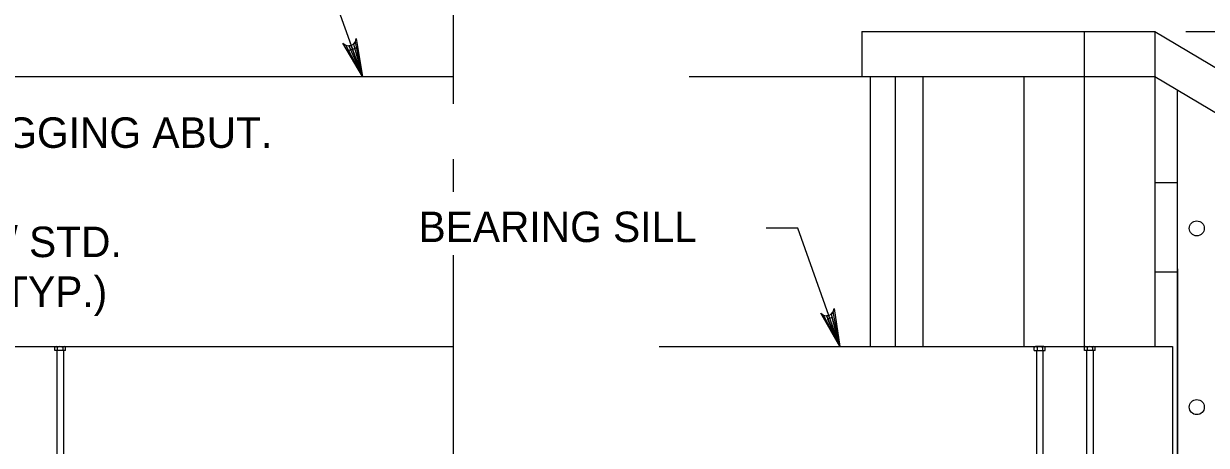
# Model space of a CAD drawing. Extents: x 635440 to 640306, y 296653 to 298484.
# Drawn here: x 639576.7 to 639693.2, y 296832.1 to 296873.6 of the extents above; entities that cross this region are included whole.
import ezdxf

# ---------------------------------------------------------------- set-up
doc = ezdxf.new("R2010")
doc.units = 0
for name, color, linetype in [('3', 7, 'Continuous'), ('4', 7, 'Continuous'), ('5', 7, 'Continuous')]:
    doc.layers.add(name, color=color, linetype=linetype)

msp = doc.modelspace()

# ---------------------------------------------------------------- linework, layer by layer
at = {"layer": '3'}
for p, q in [((639659.26, 296872.79), (639688.15, 296872.79)), ((639659.26, 296872.79), (639659.26, 296868.36)), ((639681.17, 296872.79), (639681.17, 296868.36)), ((639688.15, 296872.79), (639776.08, 296820.36)), ((639688.15, 296872.79), (639688.15, 296868.36)), ((639483.38, 296868.36), (639618.98, 296868.36)), ((639642.25, 296868.36), (639688.15, 296868.36)), ((639660.08, 296868.36), (639660.08, 296841.79)), ((639662.54, 296868.36), (639662.54, 296841.79)), ((639665.29, 296868.36), (639665.29, 296841.79)), ((639675.24, 296868.36), (639675.24, 296841.79)), ((639681.17, 296868.36), (639681.17, 296841.79)), ((639688.15, 296868.36), (639776.08, 296815.93)), ((639688.15, 296868.36), (639688.15, 296841.79)), ((639690.39, 296787.53), (639690.39, 296867.02)), ((639690.39, 296857.89), (639688.15, 296857.89)), ((639690.39, 296849.1), (639688.15, 296849.1)), ((639462.25, 296841.79), (639618.98, 296841.79)), ((639579.72, 296841.39), (639579.72, 296841.69)), ((639580.78, 296841.39), (639579.72, 296841.39)), ((639579.84, 296841.79), (639580.65, 296841.79)), ((639579.88, 296841.78), (639579.88, 296841.78)), ((639579.89, 296841.78), (639579.89, 296841.78)), ((639579.91, 296841.78), (639579.91, 296841.78)), ((639579.91, 296841.77), (639579.91, 296841.77)), ((639579.92, 296841.78), (639579.92, 296841.78)), ((639579.92, 296841.39), (639579.92, 296830.89)), ((639579.93, 296841.77), (639579.93, 296841.77)), ((639579.94, 296841.78), (639579.94, 296841.78)), ((639579.94, 296841.75), (639579.94, 296841.75)), ((639579.95, 296841.78), (639579.95, 296841.78)), ((639579.95, 296841.77), (639579.95, 296841.77)), ((639579.95, 296841.75), (639579.95, 296841.75)), ((639579.96, 296841.77), (639579.96, 296841.77)), ((639579.96, 296841.74), (639579.96, 296841.74)), ((639579.97, 296841.78), (639579.97, 296841.78)), ((639579.97, 296841.77), (639579.97, 296841.77)), ((639579.97, 296841.75), (639579.97, 296841.75)), ((639579.97, 296841.74), (639579.97, 296841.74)), ((639579.97, 296841.72), (639579.97, 296841.72)), ((639579.97, 296841.71), (639579.97, 296841.71)), ((639579.97, 296841.69), (639579.97, 296841.39)), ((639579.98, 296841.78), (639579.98, 296841.78)), ((639579.98, 296841.77), (639579.98, 296841.77)), ((639579.98, 296841.75), (639579.98, 296841.75)), ((639579.98, 296841.74), (639579.98, 296841.74)), ((639579.98, 296841.72), (639579.98, 296841.72)), ((639579.98, 296841.71), (639579.98, 296841.71)), ((639579.99, 296841.77), (639579.99, 296841.77)), ((639579.99, 296841.74), (639579.99, 296841.74)), ((639579.99, 296841.71), (639579.99, 296841.71)), ((639580, 296841.78), (639580, 296841.78)), ((639580, 296841.75), (639580, 296841.75)), ((639580, 296841.72), (639580, 296841.72)), ((639580.01, 296841.78), (639580.01, 296841.78)), ((639580.01, 296841.77), (639580.01, 296841.77)), ((639580.01, 296841.75), (639580.01, 296841.75)), ((639580.01, 296841.74), (639580.01, 296841.74)), ((639580.01, 296841.72), (639580.01, 296841.72)), ((639580.02, 296841.77), (639580.02, 296841.77)), ((639580.02, 296841.74), (639580.02, 296841.74)), ((639580.03, 296841.78), (639580.03, 296841.78)), ((639580.03, 296841.77), (639580.03, 296841.77)), ((639580.03, 296841.75), (639580.03, 296841.75)), ((639580.03, 296841.74), (639580.03, 296841.74)), ((639580.04, 296841.78), (639580.04, 296841.78)), ((639580.04, 296841.75), (639580.04, 296841.75)), ((639580.05, 296841.77), (639580.05, 296841.77)), ((639580.06, 296841.78), (639580.06, 296841.78)), ((639580.06, 296841.77), (639580.06, 296841.77)), ((639580.06, 296841.75), (639580.06, 296841.75)), ((639580.07, 296841.78), (639580.07, 296841.78)), ((639580.07, 296841.75), (639580.07, 296841.75)), ((639580.08, 296841.77), (639580.08, 296841.77)), ((639580.09, 296841.78), (639580.09, 296841.78)), ((639580.1, 296841.78), (639580.1, 296841.78)), ((639580.1, 296841.77), (639580.1, 296841.77)), ((639580.11, 296841.77), (639580.11, 296841.77)), ((639580.12, 296841.78), (639580.12, 296841.78)), ((639580.13, 296841.78), (639580.13, 296841.78)), ((639580.15, 296841.78), (639580.15, 296841.78)), ((639580.16, 296841.78), (639580.16, 296841.78)), ((639580.18, 296841.78), (639580.18, 296841.78)), ((639580.31, 296841.78), (639580.31, 296841.78)), ((639580.32, 296841.78), (639580.32, 296841.78)), ((639580.34, 296841.78), (639580.34, 296841.78)), ((639580.35, 296841.78), (639580.35, 296841.78)), ((639580.37, 296841.78), (639580.37, 296841.78)), ((639580.37, 296841.77), (639580.37, 296841.77)), ((639580.38, 296841.78), (639580.38, 296841.78)), ((639580.39, 296841.77), (639580.39, 296841.77)), ((639580.4, 296841.78), (639580.4, 296841.78)), ((639580.41, 296841.78), (639580.41, 296841.78)), ((639580.41, 296841.77), (639580.41, 296841.77)), ((639580.41, 296841.75), (639580.41, 296841.75)), ((639580.42, 296841.77), (639580.42, 296841.77)), ((639580.43, 296841.78), (639580.43, 296841.78)), ((639580.43, 296841.77), (639580.43, 296841.77)), ((639580.43, 296841.75), (639580.43, 296841.75)), ((639580.44, 296841.78), (639580.44, 296841.78)), ((639580.44, 296841.75), (639580.44, 296841.75)), ((639580.45, 296841.77), (639580.45, 296841.77)), ((639580.45, 296841.74), (639580.45, 296841.74)), ((639580.46, 296841.78), (639580.46, 296841.78)), ((639580.46, 296841.77), (639580.46, 296841.77)), ((639580.46, 296841.75), (639580.46, 296841.75)), ((639580.46, 296841.74), (639580.46, 296841.74)), ((639580.47, 296841.78), (639580.47, 296841.78)), ((639580.47, 296841.75), (639580.47, 296841.75)), ((639580.47, 296841.72), (639580.47, 296841.72)), ((639580.48, 296841.77), (639580.48, 296841.77)), ((639580.48, 296841.74), (639580.48, 296841.74)), ((639580.49, 296841.78), (639580.49, 296841.78)), ((639580.49, 296841.77), (639580.49, 296841.77)), ((639580.49, 296841.75), (639580.49, 296841.75)), ((639580.49, 296841.74), (639580.49, 296841.74)), ((639580.49, 296841.72), (639580.49, 296841.72)), ((639580.49, 296841.71), (639580.49, 296841.71)), ((639580.5, 296841.78), (639580.5, 296841.78)), ((639580.5, 296841.75), (639580.5, 296841.75)), ((639580.5, 296841.72), (639580.5, 296841.72)), ((639580.51, 296841.77), (639580.51, 296841.77)), ((639580.51, 296841.74), (639580.51, 296841.74)), ((639580.51, 296841.71), (639580.51, 296841.71)), ((639580.51, 296841.69), (639580.51, 296841.39)), ((639580.52, 296841.78), (639580.52, 296841.78)), ((639580.52, 296841.77), (639580.52, 296841.77)), ((639580.52, 296841.75), (639580.52, 296841.75)), ((639580.52, 296841.74), (639580.52, 296841.74)), ((639580.52, 296841.72), (639580.52, 296841.72)), ((639580.53, 296841.78), (639580.53, 296841.78)), ((639580.53, 296841.75), (639580.53, 296841.75)), ((639580.54, 296841.77), (639580.54, 296841.77)), ((639580.55, 296841.78), (639580.55, 296841.78)), ((639580.55, 296841.77), (639580.55, 296841.77)), ((639580.55, 296841.75), (639580.55, 296841.75)), ((639580.56, 296841.78), (639580.56, 296841.78)), ((639580.57, 296841.78), (639580.57, 296841.78)), ((639580.57, 296841.77), (639580.57, 296841.77)), ((639580.58, 296841.39), (639580.58, 296830.89)), ((639580.59, 296841.78), (639580.59, 296841.78)), ((639580.6, 296841.78), (639580.6, 296841.78)), ((639580.78, 296841.39), (639580.78, 296841.69)), ((639639.28, 296841.79), (639689.87, 296841.79)), ((639676.26, 296841.39), (639676.26, 296841.69)), ((639676.26, 296841.39), (639677.33, 296841.39)), ((639677.2, 296841.79), (639676.39, 296841.79)), ((639676.44, 296841.78), (639676.44, 296841.78)), ((639676.45, 296841.78), (639676.45, 296841.78)), ((639676.47, 296841.78), (639676.47, 296841.78)), ((639676.47, 296841.39), (639676.47, 296830.89)), ((639676.48, 296841.77), (639676.48, 296841.77)), ((639676.49, 296841.78), (639676.49, 296841.78)), ((639676.49, 296841.77), (639676.49, 296841.77)), ((639676.5, 296841.78), (639676.5, 296841.78)), ((639676.5, 296841.75), (639676.5, 296841.75)), ((639676.51, 296841.78), (639676.51, 296841.78)), ((639676.51, 296841.77), (639676.51, 296841.77)), ((639676.51, 296841.75), (639676.51, 296841.75)), ((639676.52, 296841.77), (639676.52, 296841.77)), ((639676.52, 296841.74), (639676.52, 296841.74)), ((639676.53, 296841.78), (639676.53, 296841.78)), ((639676.53, 296841.75), (639676.53, 296841.75)), ((639676.53, 296841.72), (639676.53, 296841.72)), ((639676.54, 296841.78), (639676.54, 296841.78)), ((639676.54, 296841.77), (639676.54, 296841.77)), ((639676.54, 296841.75), (639676.54, 296841.75)), ((639676.54, 296841.74), (639676.54, 296841.74)), ((639676.54, 296841.72), (639676.54, 296841.72)), ((639676.54, 296841.71), (639676.54, 296841.71)), ((639676.54, 296841.69), (639676.54, 296841.39)), ((639676.55, 296841.77), (639676.55, 296841.77)), ((639676.55, 296841.74), (639676.55, 296841.74)), ((639676.55, 296841.71), (639676.55, 296841.71)), ((639676.56, 296841.78), (639676.56, 296841.78)), ((639676.56, 296841.75), (639676.56, 296841.75)), ((639676.56, 296841.72), (639676.56, 296841.72)), ((639676.57, 296841.78), (639676.57, 296841.78)), ((639676.57, 296841.77), (639676.57, 296841.77)), ((639676.57, 296841.75), (639676.57, 296841.75)), ((639676.57, 296841.74), (639676.57, 296841.74)), ((639676.57, 296841.72), (639676.57, 296841.72)), ((639676.58, 296841.77), (639676.58, 296841.77)), ((639676.58, 296841.74), (639676.58, 296841.74)), ((639676.59, 296841.78), (639676.59, 296841.78)), ((639676.59, 296841.75), (639676.59, 296841.75)), ((639676.6, 296841.78), (639676.6, 296841.78)), ((639676.6, 296841.77), (639676.6, 296841.77)), ((639676.6, 296841.75), (639676.6, 296841.75)), ((639676.6, 296841.74), (639676.6, 296841.74)), ((639676.61, 296841.77), (639676.61, 296841.77)), ((639676.62, 296841.78), (639676.62, 296841.78)), ((639676.62, 296841.77), (639676.62, 296841.77)), ((639676.62, 296841.75), (639676.62, 296841.75)), ((639676.63, 296841.78), (639676.63, 296841.78)), ((639676.63, 296841.75), (639676.63, 296841.75)), ((639676.64, 296841.77), (639676.64, 296841.77)), ((639676.65, 296841.78), (639676.65, 296841.78)), ((639676.65, 296841.77), (639676.65, 296841.77)), ((639676.66, 296841.78), (639676.66, 296841.78)), ((639676.67, 296841.77), (639676.67, 296841.77)), ((639676.68, 296841.78), (639676.68, 296841.78)), ((639676.69, 296841.78), (639676.69, 296841.78)), ((639676.71, 296841.78), (639676.71, 296841.78)), ((639676.72, 296841.78), (639676.72, 296841.78)), ((639676.74, 296841.78), (639676.74, 296841.78)), ((639676.87, 296841.78), (639676.87, 296841.78)), ((639676.88, 296841.78), (639676.88, 296841.78)), ((639676.9, 296841.78), (639676.9, 296841.78)), ((639676.91, 296841.78), (639676.91, 296841.78)), ((639676.93, 296841.78), (639676.93, 296841.78)), ((639676.94, 296841.78), (639676.94, 296841.78)), ((639676.94, 296841.77), (639676.94, 296841.77)), ((639676.95, 296841.77), (639676.95, 296841.77)), ((639676.96, 296841.78), (639676.96, 296841.78)), ((639676.96, 296841.77), (639676.96, 296841.77)), ((639676.97, 296841.78), (639676.97, 296841.78)), ((639676.97, 296841.75), (639676.97, 296841.75)), ((639676.98, 296841.77), (639676.98, 296841.77)), ((639676.99, 296841.78), (639676.99, 296841.78)), ((639676.99, 296841.77), (639676.99, 296841.77)), ((639676.99, 296841.75), (639676.99, 296841.75)), ((639677, 296841.78), (639677, 296841.78)), ((639677, 296841.75), (639677, 296841.75)), ((639677.01, 296841.77), (639677.01, 296841.77)), ((639677.01, 296841.74), (639677.01, 296841.74)), ((639677.02, 296841.78), (639677.02, 296841.78)), ((639677.02, 296841.77), (639677.02, 296841.77)), ((639677.02, 296841.75), (639677.02, 296841.75)), ((639677.02, 296841.74), (639677.02, 296841.74)), ((639677.03, 296841.78), (639677.03, 296841.78)), ((639677.03, 296841.75), (639677.03, 296841.75)), ((639677.03, 296841.72), (639677.03, 296841.72)), ((639677.04, 296841.77), (639677.04, 296841.77)), ((639677.04, 296841.74), (639677.04, 296841.74)), ((639677.05, 296841.78), (639677.05, 296841.78)), ((639677.05, 296841.77), (639677.05, 296841.77)), ((639677.05, 296841.75), (639677.05, 296841.75)), ((639677.05, 296841.74), (639677.05, 296841.74)), ((639677.05, 296841.72), (639677.05, 296841.72)), ((639677.05, 296841.71), (639677.05, 296841.71)), ((639677.06, 296841.78), (639677.06, 296841.78)), ((639677.06, 296841.75), (639677.06, 296841.75)), ((639677.06, 296841.72), (639677.06, 296841.72)), ((639677.07, 296841.77), (639677.07, 296841.77)), ((639677.07, 296841.77), (639677.07, 296841.77)), ((639677.07, 296841.74), (639677.07, 296841.74)), ((639677.07, 296841.74), (639677.07, 296841.74)), ((639677.07, 296841.71), (639677.07, 296841.71)), ((639677.07, 296841.71), (639677.07, 296841.71)), ((639677.07, 296841.69), (639677.07, 296841.39)), ((639677.08, 296841.78), (639677.08, 296841.78)), ((639677.08, 296841.75), (639677.08, 296841.75)), ((639677.08, 296841.72), (639677.08, 296841.72)), ((639677.09, 296841.78), (639677.09, 296841.78)), ((639677.09, 296841.77), (639677.09, 296841.77)), ((639677.09, 296841.75), (639677.09, 296841.75)), ((639677.09, 296841.74), (639677.09, 296841.74)), ((639677.1, 296841.77), (639677.1, 296841.77)), ((639677.11, 296841.78), (639677.11, 296841.78)), ((639677.11, 296841.77), (639677.11, 296841.77)), ((639677.11, 296841.75), (639677.11, 296841.75)), ((639677.12, 296841.78), (639677.12, 296841.78)), ((639677.12, 296841.39), (639677.12, 296830.89)), ((639677.13, 296841.77), (639677.13, 296841.77)), ((639677.14, 296841.78), (639677.14, 296841.78)), ((639677.15, 296841.78), (639677.15, 296841.78)), ((639677.17, 296841.78), (639677.17, 296841.78)), ((639677.33, 296841.39), (639677.33, 296841.69)), ((639681.21, 296841.39), (639681.21, 296841.69)), ((639682.27, 296841.39), (639681.21, 296841.39)), ((639681.33, 296841.79), (639682.14, 296841.79)), ((639681.37, 296841.78), (639681.37, 296841.78)), ((639681.38, 296841.78), (639681.38, 296841.78)), ((639681.4, 296841.78), (639681.4, 296841.78)), ((639681.4, 296841.77), (639681.4, 296841.77)), ((639681.41, 296841.78), (639681.41, 296841.78)), ((639681.41, 296841.39), (639681.41, 296830.89)), ((639681.42, 296841.77), (639681.42, 296841.77)), ((639681.43, 296841.78), (639681.43, 296841.78)), ((639681.43, 296841.77), (639681.43, 296841.77)), ((639681.43, 296841.75), (639681.43, 296841.75)), ((639681.44, 296841.78), (639681.44, 296841.78)), ((639681.44, 296841.75), (639681.44, 296841.75)), ((639681.45, 296841.77), (639681.45, 296841.77)), ((639681.45, 296841.74), (639681.45, 296841.74)), ((639681.46, 296841.78), (639681.46, 296841.78)), ((639681.46, 296841.77), (639681.46, 296841.77)), ((639681.46, 296841.75), (639681.46, 296841.75)), ((639681.46, 296841.74), (639681.46, 296841.74)), ((639681.46, 296841.72), (639681.46, 296841.72)), ((639681.46, 296841.71), (639681.46, 296841.71)), ((639681.46, 296841.69), (639681.46, 296841.39)), ((639681.47, 296841.78), (639681.47, 296841.78)), ((639681.47, 296841.77), (639681.47, 296841.77)), ((639681.47, 296841.75), (639681.47, 296841.75)), ((639681.47, 296841.74), (639681.47, 296841.74)), ((639681.47, 296841.72), (639681.47, 296841.72)), ((639681.47, 296841.71), (639681.47, 296841.71)), ((639681.48, 296841.77), (639681.48, 296841.77)), ((639681.48, 296841.74), (639681.48, 296841.74)), ((639681.48, 296841.71), (639681.48, 296841.71)), ((639681.49, 296841.78), (639681.49, 296841.78)), ((639681.49, 296841.75), (639681.49, 296841.75)), ((639681.49, 296841.72), (639681.49, 296841.72)), ((639681.5, 296841.78), (639681.5, 296841.78)), ((639681.5, 296841.77), (639681.5, 296841.77)), ((639681.5, 296841.75), (639681.5, 296841.75)), ((639681.5, 296841.74), (639681.5, 296841.74)), ((639681.5, 296841.72), (639681.5, 296841.72)), ((639681.51, 296841.77), (639681.51, 296841.77)), ((639681.51, 296841.74), (639681.51, 296841.74)), ((639681.52, 296841.78), (639681.52, 296841.78)), ((639681.52, 296841.77), (639681.52, 296841.77)), ((639681.52, 296841.75), (639681.52, 296841.75)), ((639681.52, 296841.74), (639681.52, 296841.74)), ((639681.53, 296841.78), (639681.53, 296841.78)), ((639681.53, 296841.75), (639681.53, 296841.75)), ((639681.54, 296841.77), (639681.54, 296841.77)), ((639681.55, 296841.78), (639681.55, 296841.78)), ((639681.55, 296841.77), (639681.55, 296841.77)), ((639681.55, 296841.75), (639681.55, 296841.75)), ((639681.56, 296841.78), (639681.56, 296841.78)), ((639681.56, 296841.75), (639681.56, 296841.75)), ((639681.57, 296841.77), (639681.57, 296841.77)), ((639681.58, 296841.78), (639681.58, 296841.78)), ((639681.58, 296841.77), (639681.58, 296841.77)), ((639681.59, 296841.78), (639681.59, 296841.78)), ((639681.6, 296841.77), (639681.6, 296841.77)), ((639681.61, 296841.78), (639681.61, 296841.78)), ((639681.62, 296841.78), (639681.62, 296841.78)), ((639681.64, 296841.78), (639681.64, 296841.78)), ((639681.65, 296841.78), (639681.65, 296841.78)), ((639681.66, 296841.78), (639681.66, 296841.78)), ((639681.8, 296841.78), (639681.8, 296841.78)), ((639681.81, 296841.78), (639681.81, 296841.78)), ((639681.83, 296841.78), (639681.83, 296841.78)), ((639681.84, 296841.78), (639681.84, 296841.78)), ((639681.86, 296841.78), (639681.86, 296841.78)), ((639681.86, 296841.77), (639681.86, 296841.77)), ((639681.87, 296841.78), (639681.87, 296841.78)), ((639681.88, 296841.77), (639681.88, 296841.77)), ((639681.89, 296841.78), (639681.89, 296841.78)), ((639681.89, 296841.77), (639681.89, 296841.77)), ((639681.9, 296841.78), (639681.9, 296841.78)), ((639681.9, 296841.75), (639681.9, 296841.75)), ((639681.91, 296841.77), (639681.91, 296841.77)), ((639681.92, 296841.78), (639681.92, 296841.78)), ((639681.92, 296841.77), (639681.92, 296841.77)), ((639681.92, 296841.75), (639681.92, 296841.75)), ((639681.93, 296841.78), (639681.93, 296841.78)), ((639681.93, 296841.75), (639681.93, 296841.75)), ((639681.94, 296841.77), (639681.94, 296841.77)), ((639681.94, 296841.74), (639681.94, 296841.74)), ((639681.95, 296841.78), (639681.95, 296841.78)), ((639681.95, 296841.77), (639681.95, 296841.77)), ((639681.95, 296841.75), (639681.95, 296841.75)), ((639681.95, 296841.74), (639681.95, 296841.74)), ((639681.96, 296841.78), (639681.96, 296841.78)), ((639681.96, 296841.75), (639681.96, 296841.75)), ((639681.96, 296841.72), (639681.96, 296841.72)), ((639681.97, 296841.78), (639681.97, 296841.78)), ((639681.97, 296841.77), (639681.97, 296841.77)), ((639681.97, 296841.75), (639681.97, 296841.75)), ((639681.97, 296841.74), (639681.97, 296841.74)), ((639681.97, 296841.72), (639681.97, 296841.72)), ((639681.98, 296841.77), (639681.98, 296841.77)), ((639681.98, 296841.74), (639681.98, 296841.74)), ((639681.98, 296841.71), (639681.98, 296841.71)), ((639681.99, 296841.78), (639681.99, 296841.78)), ((639681.99, 296841.75), (639681.99, 296841.75)), ((639681.99, 296841.72), (639681.99, 296841.72)), ((639682, 296841.78), (639682, 296841.78)), ((639682, 296841.77), (639682, 296841.77)), ((639682, 296841.75), (639682, 296841.75)), ((639682, 296841.74), (639682, 296841.74)), ((639682, 296841.72), (639682, 296841.72)), ((639682, 296841.71), (639682, 296841.71)), ((639682, 296841.69), (639682, 296841.39)), ((639682.01, 296841.77), (639682.01, 296841.77)), ((639682.01, 296841.74), (639682.01, 296841.74)), ((639682.02, 296841.78), (639682.02, 296841.78)), ((639682.02, 296841.75), (639682.02, 296841.75)), ((639682.03, 296841.77), (639682.03, 296841.77)), ((639682.04, 296841.78), (639682.04, 296841.78)), ((639682.04, 296841.77), (639682.04, 296841.77)), ((639682.04, 296841.75), (639682.04, 296841.75)), ((639682.05, 296841.78), (639682.05, 296841.78)), ((639682.06, 296841.78), (639682.06, 296841.78)), ((639682.06, 296841.77), (639682.06, 296841.77)), ((639682.07, 296841.39), (639682.07, 296830.89)), ((639682.08, 296841.78), (639682.08, 296841.78)), ((639682.09, 296841.78), (639682.09, 296841.78)), ((639682.27, 296841.39), (639682.27, 296841.69)), ((639689.87, 296841.79), (639689.87, 296822.59))]:
    msp.add_line(p, q, dxfattribs=at)
for centre in [(639692.28, 296853.42), (639692.28, 296835.83)]:
    msp.add_circle(centre, 0.738, dxfattribs=at)
for centre, radius, start, end in [((639579.85, 296841.65), 0.135, 17.4518, 162.5482), ((639580.24, 296841.36), 0.424, 51.05, 128.95), ((639580.65, 296841.64), 0.148, 91.8271, 158.7131), ((639580.65, 296841.64), 0.148, 21.2869, 91.8271), ((639676.4, 296841.64), 0.148, 88.1729, 158.7131), ((639676.4, 296841.64), 0.148, 21.2869, 88.1729), ((639676.8, 296841.36), 0.424, 51.05, 128.95), ((639677.2, 296841.65), 0.135, 17.4518, 162.5482), ((639681.34, 296841.65), 0.135, 17.4518, 162.5482), ((639681.73, 296841.36), 0.424, 51.05, 128.95), ((639682.13, 296841.64), 0.148, 91.8271, 158.7131), ((639682.13, 296841.64), 0.148, 21.2869, 91.8271)]:
    msp.add_arc(centre, radius, start, end, dxfattribs=at)
at = {"layer": '4'}
for p, q in [((639610.04, 296868.36), (639600.85, 296894.02)), ((639618.98, 296890.38), (639618.98, 296865.67)), ((639691.19, 296872.79), (639697.19, 296872.79)), ((639618.98, 296860.22), (639618.98, 296857.02)), ((639618.98, 296850.77), (639618.98, 296749.87)), ((639690.39, 296849.43), (639690.39, 296802.35))]:
    msp.add_line(p, q, dxfattribs=at)
for points in [[(639610.04, 296868.36), (639608.13, 296871.63), (639608.41, 296871.43), (639608.7, 296871.37), (639608.95, 296871.42), (639609.17, 296871.54), (639609.35, 296871.77), (639609.44, 296872.11), (639610.04, 296868.36), (639609.35, 296871.77), (639609.17, 296871.54), (639610.04, 296868.36), (639608.95, 296871.42), (639608.7, 296871.37), (639610.04, 296868.36), (639608.41, 296871.43)], [(639657.09, 296841.79), (639652.97, 296853.44), (639649.85, 296853.44)], [(639657.09, 296841.79), (639655.21, 296845.08), (639655.49, 296844.87), (639655.77, 296844.81), (639656.02, 296844.86), (639656.25, 296844.98), (639656.43, 296845.2), (639656.53, 296845.54), (639657.09, 296841.79), (639656.43, 296845.2), (639656.25, 296844.98), (639657.09, 296841.79), (639656.02, 296844.86), (639655.77, 296844.81), (639657.09, 296841.79), (639655.49, 296844.87)]]:
    msp.add_lwpolyline(points, dxfattribs=at)
for points in [[(639609.53, 296871.19), (639608.64, 296870.88), (639610.02, 296868.36)], [(639657.09, 296841.79), (639656.35, 296844.66), (639655.89, 296844.49)]]:
    msp.add_lwpolyline(points, close=True, dxfattribs=at)

# ---------------------------------------------------------------- texts
for s, p in [('BEARING SILL', (639615.58, 296852.07)), ('12.7 (1/2")  BOLT W/ STD.', (639538.76, 296850.59)), ('NUT & WASHERS (TYP.)', (639538.76, 296845.69))]:
    msp.add_text(s, height=3.0001, dxfattribs=at).set_placement(p)
at = {"layer": '5'}
msp.add_text('76x305 (3"x12") TIMBER LAGGING ABUT.', height=3.0001, dxfattribs=at).set_placement((639524.07, 296861.34))

doc.saveas('drawing.dxf')
